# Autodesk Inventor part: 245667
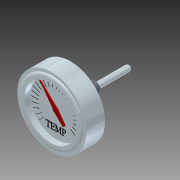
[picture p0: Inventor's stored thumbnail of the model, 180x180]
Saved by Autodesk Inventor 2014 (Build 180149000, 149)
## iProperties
Shininess: 20.0
Length Units: 11272
Angle Units: 11279
Time Units: 11290
Mass Units: 11286
Length Display Precision: 3
Angle Display Precision: 2
Company: Autodesk, Inc.
Created: 2002-06
Part Number: 245667
Material: Stainless Steel 316
Description: GAUGE, TEMP
Document SubType Name: Modeling
Designer: Autodesk, Inc.
Density: 8.182 g/cm^3
Mass: 724.873 g
Surface Area: 174.45 cm^2
Volume: 88.5936 cm^3
Appearance: Stainless Steel
Density: 0.0
Volumn: 0.0
Area: 0.0
PropertySet Name: Model Information
Control State: 0
Master: False
Checked Out: False
Last Check In By: JT
Last Check In Date: 2003-06-20
Title: GAUGE, TEMP
Author: Autodesk, Inc.
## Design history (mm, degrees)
sketch "Sketch1"
  geometry: L1 (-23.813, 28.575)-(-23.813, 31.75); L2 (-22.225, 34.925)-(-22.225, 38.1); L3 (-22.225, 38.1)-(-1.588, 38.1); L4 (-1.588, 38.1)-(-1.588, 12.7); L5 (0, 11.113)-(0, 6.35); L6 (0, 6.35)-(25.4, 6.35); L7 (25.4, 6.35)-(25.4, 3.175); L8 (25.4, 3.175)-(61.119, 3.175); L9 (63.5, 0.794)-(63.5, 0); L10 (0, 0)-(-65.162, 0); L11 (-23.813, 28.575)-(-17.336, 28.575); L12 (-17.336, 28.575)-(-17.336, 0); L13 (63.5, 0)-(-17.336, 0); A1 r 3.969 centre (-19.844, 31.75) between (-22.225, 34.925) and (-23.813, 31.75); A2 r 1.587 centre (-1.587, 11.113) between (0, 11.113) and (-1.588, 12.7); A3 r 2.381 centre (61.119, 0.794) between (63.5, 0.794) and (61.119, 3.175); 1 further point
  constraints: 26 end point, 8 parallel, 6 point on circle, 4 point on line, 4 tangent, 3 centre point, 3 perpendicular, 1 collinear, 1 horizontal alignment, 1 vertical, 1 vertical alignment
  dimensions: "d4" = 76.2 diameter of L3 L10; "d5" = 1.5875 distance between parallel lines of L2 L1; "d6" = 57.15 diameter of L11 L10; "d7" = 3.175 distance of L2.start L2.end; "d8" = 3.175 distance of L1.start L1.end; "d9" = 1.5875 radius of A2; "d10" = 25.4 diameter of L4.end L10; "d11" = 12.7 diameter of L6 L10; "d12" = 22.225 distance between parallel lines of L2 L5; "d13" = 6.477 distance of L1.start L11.end; "d14" = 25.4 distance of L5.end L6.end; "d15" = 38.1 distance of L7.end point (63.5, 3.175); "d16" = 6.35 diameter of L8 L10; "d17" = 2.38125 radius of A3
revolve "Revolution1" sketch "Sketch1" stored, may be unused: angle "d18" = 90 deg
sketch "Sketch6"
  geometry: L1 (-19.001, -19.708)-(-13.339, -13.89); L2 (-13.339, -13.89)-(-13.521, -13.713); L3 (-13.521, -13.713)-(-19.183, -19.531); L4 (-19.183, -19.531)-(-19.001, -19.708); L5 (0, 0)-(-13.43, -13.801); C1 r 28.575 at (0, 0) reference
  constraints: 10 end point, 2 parallel, 2 perpendicular, 1 midpoint
  dimensions: "d32" = 0.254 distance between parallel lines of L3 L1
extrude "Extrusion6" join sketch "Sketch6" distance "d30" = 0.254; taper "d31" = 0 deg
sketch "Sketch7"
  geometry: L1 (-13.788, 13.444)-(-19.564, 19.15) reference; L2 (-2.69, 0.085)-(-16.936, 19.723); L3 (-16.936, 19.723)-(0.323, 2.672); L4 (2.672, 0.324)-(10.438, -10.382); L5 (10.438, -10.382)-(8.462, -11.815); L6 (8.462, -11.815)-(-0.946, -2.519); C1 r 28.575 at (0, 0) reference; A1 r 2.691 centre (0, 0) between (-2.69, 0.085) and (-0.946, -2.519); A2 r 2.691 centre (0, 0) between (2.672, 0.324) and (0.323, 2.672)
  constraints: 10 end point, 4 point on circle, 3 parallel, 2 centre point, 2 equal length, 1 coincident, 1 concentric, 1 perpendicular
extrude "Extrusion7" join sketch "Sketch7" distance "d36" = 1.27; taper "d37" = 0 deg
thread "Thread1" dims "d38" = 25.4, "d39" = 0
sketch "Sketch9"
  geometry: L1 (-19.255, -0.316)-(-27.373, -0.396) reference; L2 (-11.209, -20.374)-(11.264, -20.153); L3 (-6.343, -16.112)-(-6.533, -16.112); L4 (-7.948, -14.861)-(-8.449, -14.861); L5 (-8.449, -14.861)-(-8.449, -19.788); L6 (-7.525, -20.745)-(-7.525, -20.918); L7 (-7.525, -20.918)-(-9.898, -20.918); L8 (-9.898, -20.918)-(-9.898, -20.745); L9 (-9.001, -19.667)-(-9.001, -14.861); L10 (-9.001, -14.861)-(-9.518, -14.861); L11 (-10.925, -16.112)-(-11.123, -16.112); L12 (-11.123, -16.112)-(-11.071, -14.568); L13 (-11.071, -14.568)-(-6.395, -14.568); L14 (-6.395, -14.568)-(-6.343, -16.112); L15 (-1.216, -19.365)-(-1.578, -20.918); L16 (-1.578, -20.918)-(-6.073, -20.918); L17 (-6.073, -20.918)-(-6.073, -20.745); L18 (-5.219, -19.857)-(-5.219, -15.638); L19 (-6.073, -14.74)-(-6.073, -14.568); L20 (-6.073, -14.568)-(-1.647, -14.568); L21 (-1.647, -14.568)-(-1.621, -15.862); L22 (-1.621, -15.862)-(-1.802, -15.862); L23 (-3.088, -14.861)-(-4.33, -14.861); L24 (-4.675, -15.189)-(-4.675, -17.406); L25 (-4.675, -17.406)-(-3.26, -17.406); L26 (-2.303, -16.518)-(-2.122, -16.518); L27 (-2.122, -16.518)-(-2.122, -18.666); L28 (-2.122, -18.666)-(-2.303, -18.666); L29 (-3.26, -17.76)-(-4.675, -17.76); L30 (-4.675, -17.76)-(-4.675, -20.159); L31 (-1.397, -19.365)-(-1.216, -19.365); L32 (6.017, -20.901)-(3.765, -20.901); L33 (3.765, -20.901)-(3.765, -20.728); L34 (4.637, -19.719)-(4.637, -15.025); L35 (4.637, -15.025)-(4.552, -15.077); L36 (4.552, -15.077)-(2.327, -20.901); L37 (2.327, -20.901)-(2.258, -20.901); L38 (2.258, -20.901)-(0.078, -15.086); L39 (0.078, -15.086)-(0.018, -15.068); L40 (0.018, -15.068)-(0.018, -19.529); L41 (0.872, -20.728)-(0.872, -20.901); L42 (0.872, -20.901)-(-1.009, -20.901); L43 (-1.009, -20.901)-(-1.009, -20.728); L44 (-0.258, -19.529)-(-0.258, -15.569); L45 (-0.991, -14.715)-(-0.991, -14.551); L46 (-0.991, -14.551)-(0.487, -14.551); L47 (0.487, -14.551)-(2.448, -19.857); L48 (2.448, -19.857)-(4.461, -14.551); L49 (4.461, -14.551)-(6.017, -14.551); L50 (6.017, -14.551)-(6.017, -14.715); L51 (5.163, -15.569)-(5.163, -19.839); L52 (6.017, -20.728)-(6.017, -20.901); L53 (7.748, -18.062)-(7.748, -19.77); L54 (8.654, -20.728)-(8.654, -20.901); L55 (8.654, -20.901)-(6.385, -20.901); L56 (6.385, -20.901)-(6.385, -20.728); L57 (7.205, -19.65)-(7.205, -15.62); L58 (6.385, -14.723)-(6.385, -14.551); L59 (6.385, -14.551)-(8.577, -14.551); L60 (7.748, -15.241)-(7.748, -17.751); 82 further points
  constraints: 118 end point, 1 parallel, 156 other
extrude "Extrusion8" join sketch "Sketch9" distance "d40" = 0.508; taper "d41" = 0 deg
body "Solid1"
pattern_circular "Circular Pattern1" dims angle "d35" = 260 deg
